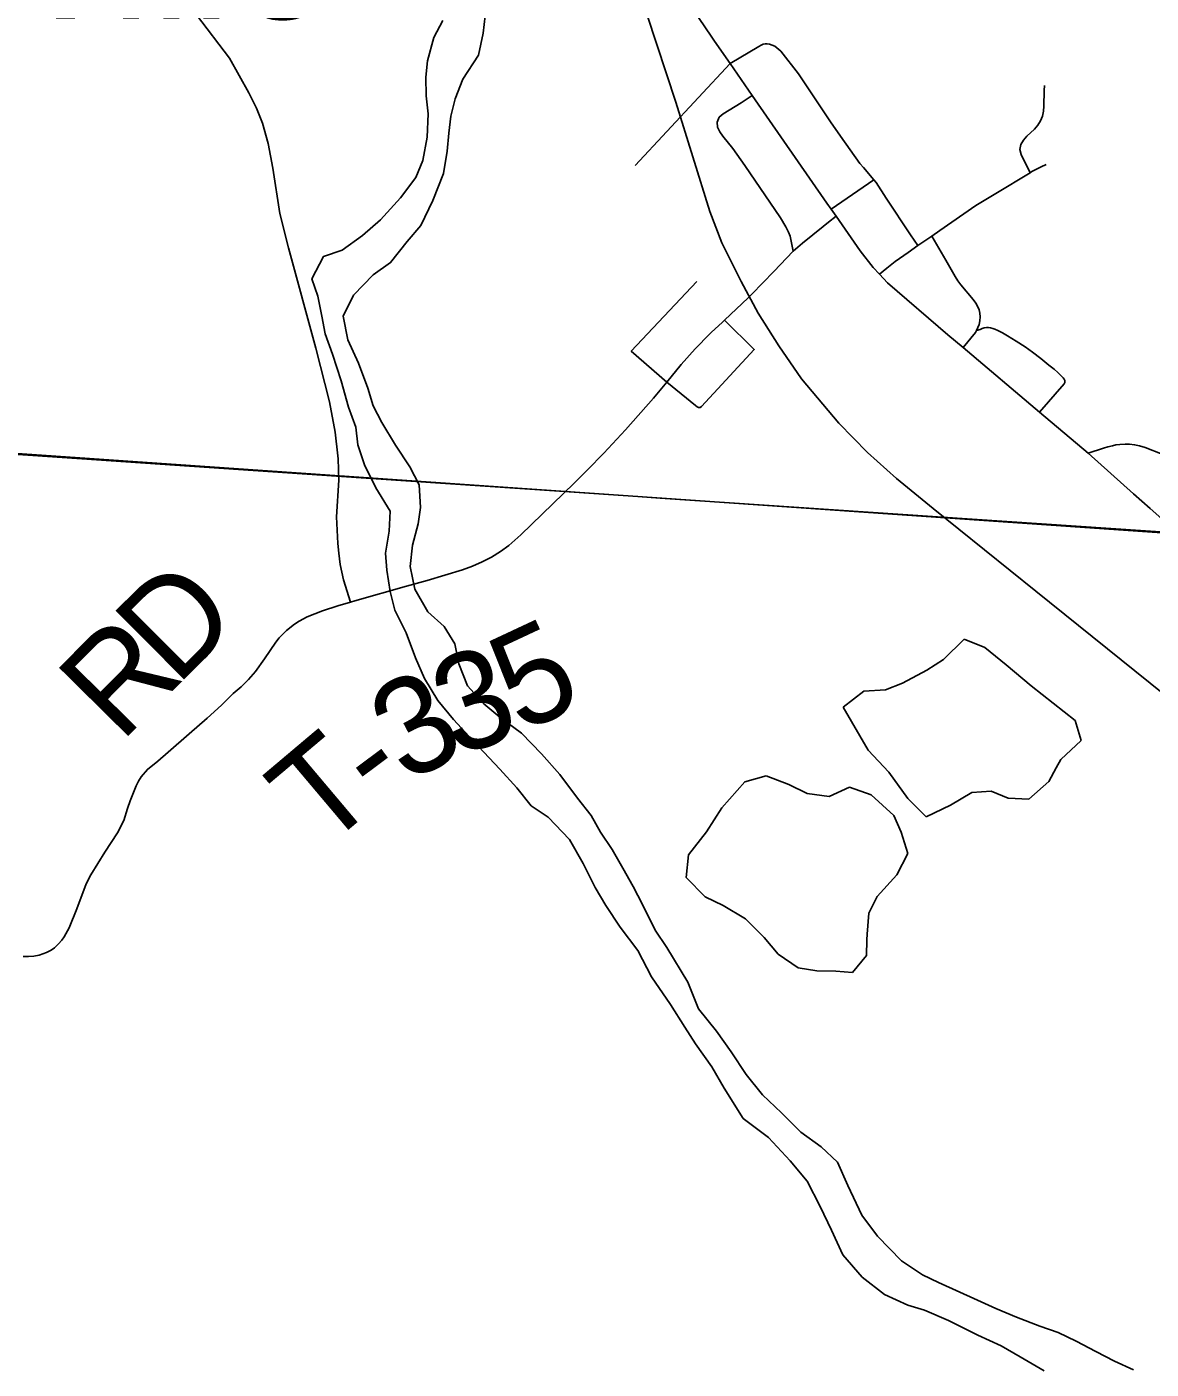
# Model space of a CAD drawing. Extents: x 39.8 to 73.8, y 13 to 35.
# Drawn here: x 46.42 to 47.078, y 27.389 to 28.175 of the extents above; entities that cross this region are included whole.
import ezdxf

# ---------------------------------------------------------------- set-up
doc = ezdxf.new("R2010")
doc.units = 0
for name, color, linetype in [('GM_X_Corporation', 7, 'Continuous'), ('GM_X_County_Road', 7, 'Continuous'), ('GM_X_Major_River', 7, 'Continuous'), ('GM_X_Minor_Lake', 7, 'Continuous'), ('GM_X_Rail_Line', 7, 'Continuous'), ('GM_X_Township_Road', 7, 'Continuous'), ('GM_X_Township_Road_Text', 7, 'Continuous'), ('GM_X_Unincorporated_Text', 7, 'Continuous')]:
    doc.layers.add(name, color=color, linetype=linetype)

msp = doc.modelspace()

# ---------------------------------------------------------------- linework, layer by layer
at = {"layer": 'GM_X_Corporation'}
msp.add_lwpolyline([(43.33042, 29.73647), (43.27257, 28.95026), (43.2721, 28.94382), (43.21308, 28.14161), (43.99916, 28.08829), (44.12704, 28.07962), (44.14223, 28.07859), (45.30639, 27.99962), (46.17667, 27.94059), (46.60108, 27.9118), (46.7316, 27.90295), (46.77749, 27.89983), (46.79052, 27.89895), (47.09502, 27.87829), (47.51487, 27.84982)], dxfattribs=at)
for points in [[(46.28582, 28.96471), (47.30013, 28.91155), (47.3019, 28.79184), (47.22222, 27.86899), (46.24519, 27.93679)], [(43.1433, 27.06498), (48.66298, 27.06498), (48.66298, 27.78088), (47.54138, 27.84843), (47.51487, 27.84982), (47.09502, 27.87829), (46.79052, 27.89895), (46.77749, 27.89983), (46.7316, 27.90295), (46.60108, 27.9118), (46.17667, 27.94059), (45.30639, 27.99962), (44.14223, 28.07859), (44.12704, 28.07962), (43.99916, 28.08829), (43.21308, 28.14161)], [(46.16091, 27.06498), (47.18234, 27.06498), (47.22222, 27.86899), (46.24519, 27.93679)]]:
    msp.add_lwpolyline(points, close=True, dxfattribs=at)
at = {"layer": 'GM_X_County_Road'}
msp.add_lwpolyline([(46.80526, 28.19183), (46.8208, 28.16863), (46.82235, 28.16639), (46.83147, 28.15325), (46.8445, 28.13446), (46.88812, 28.07159), (46.89064, 28.06796), (46.89352, 28.06383), (46.90761, 28.04354), (46.91523, 28.03381), (46.91896, 28.02991), (46.92374, 28.0249), (46.95905, 27.99454), (46.96796, 27.98699), (47.01255, 27.94928), (47.0411, 27.92512), (47.06759, 27.90145), (47.0773, 27.89289), (47.10298, 27.87025)], dxfattribs=at)
at = {"layer": 'GM_X_Major_River'}
for p, q in [((46.68689, 28.17105), (46.68865, 28.18623)), ((46.66337, 28.17842), (46.65815, 28.16852)), ((46.65815, 28.16852), (46.65449, 28.15484)), ((46.68435, 28.15814), (46.68689, 28.17105)), ((46.65449, 28.15484), (46.65344, 28.14536)), ((46.67501, 28.14404), (46.68435, 28.15814)), ((46.65344, 28.14536), (46.65353, 28.13437)), ((46.67057, 28.13263), (46.67501, 28.14404)), ((46.65353, 28.13437), (46.65476, 28.12377)), ((46.66801, 28.12238), (46.67057, 28.13263)), ((46.65476, 28.12377), (46.65412, 28.11012)), ((46.66697, 28.11251), (46.66801, 28.12238)), ((46.66592, 28.10189), (46.66697, 28.11251)), ((46.65412, 28.11012), (46.65159, 28.09646)), ((46.66376, 28.08899), (46.66592, 28.10189)), ((46.65159, 28.09646), (46.64751, 28.08657)), ((46.65747, 28.07302), (46.66376, 28.08899)), ((46.64751, 28.08657), (46.63854, 28.07474)), ((46.63854, 28.07474), (46.62692, 28.06175)), ((46.65041, 28.05855), (46.65747, 28.07302)), ((46.62692, 28.06175), (46.61641, 28.05256)), ((46.64255, 28.04901), (46.65041, 28.05855)), ((46.61641, 28.05256), (46.60437, 28.04411)), ((46.60437, 28.04411), (46.59344, 28.04022)), ((46.63282, 28.03679), (46.64255, 28.04901)), ((46.59344, 28.04022), (46.58674, 28.02728)), ((46.62266, 28.0295), (46.63282, 28.03679)), ((46.58674, 28.02728), (46.59023, 28.01708)), ((46.61104, 28.01764), (46.62266, 28.0295)), ((46.59023, 28.01708), (46.5926, 28.00535)), ((46.60509, 28.00546), (46.61104, 28.01764)), ((46.5926, 28.00535), (46.59458, 27.99514)), ((46.60786, 27.99147), (46.60509, 28.00546)), ((46.59458, 27.99514), (46.59885, 27.98305)), ((46.61403, 27.97788), (46.60786, 27.99147)), ((46.59885, 27.98305), (46.6039, 27.96756)), ((46.61946, 27.96315), (46.61403, 27.97788)), ((46.6039, 27.96756), (46.6082, 27.95206)), ((46.62257, 27.95295), (46.61946, 27.96315)), ((46.6082, 27.95206), (46.61247, 27.94035)), ((46.62758, 27.94314), (46.62257, 27.95295)), ((46.61247, 27.94035), (46.61369, 27.93013)), ((46.63564, 27.92995), (46.62758, 27.94314)), ((46.61369, 27.93013), (46.61758, 27.91842)), ((46.64407, 27.91715), (46.63564, 27.92995)), ((46.61758, 27.91842), (46.62413, 27.90484)), ((46.64946, 27.90659), (46.64407, 27.91715)), ((46.62413, 27.90484), (46.63257, 27.89127)), ((46.65034, 27.89333), (46.64946, 27.90659)), ((46.6489, 27.88384), (46.65034, 27.89333)), ((46.63257, 27.89127), (46.63192, 27.87952)), ((46.63192, 27.87952), (46.62976, 27.86662)), ((46.64561, 27.87131), (46.6489, 27.88384)), ((46.6442, 27.85879), (46.64561, 27.87131)), ((46.62976, 27.86662), (46.6306, 27.85677)), ((46.6306, 27.85677), (46.6326, 27.84428)), ((46.64697, 27.84555), (46.6442, 27.85879)), ((46.65465, 27.83236), (46.64697, 27.84555)), ((46.6326, 27.84428), (46.63534, 27.83332)), ((46.63534, 27.83332), (46.64189, 27.82012)), ((46.66419, 27.82373), (46.65465, 27.83236)), ((46.67033, 27.81356), (46.66419, 27.82373)), ((46.64189, 27.82012), (46.64732, 27.80539)), ((46.6727, 27.80183), (46.67033, 27.81356)), ((46.64732, 27.80539), (46.65272, 27.79331)), ((46.67773, 27.78899), (46.6727, 27.80183)), ((46.65272, 27.79331), (46.6604, 27.78049)), ((46.68728, 27.77847), (46.67773, 27.78899)), ((46.6604, 27.78049), (46.66958, 27.76921)), ((46.69681, 27.7706), (46.68728, 27.77847)), ((46.66958, 27.76921), (46.68104, 27.75681)), ((46.70938, 27.76124), (46.69681, 27.7706)), ((46.72121, 27.74922), (46.70938, 27.76124)), ((46.68104, 27.75681), (46.69669, 27.74028)), ((46.73191, 27.73719), (46.72121, 27.74922)), ((46.69669, 27.74028), (46.70663, 27.72938)), ((46.74225, 27.72326), (46.73191, 27.73719)), ((46.70663, 27.72938), (46.71504, 27.71885)), ((46.75028, 27.71311), (46.74225, 27.72326)), ((46.71504, 27.71885), (46.72494, 27.71212)), ((46.72494, 27.71212), (46.73754, 27.69897)), ((46.75566, 27.7033), (46.75028, 27.71311)), ((46.73754, 27.69897), (46.74561, 27.68502)), ((46.76256, 27.69313), (46.75566, 27.7033)), ((46.76871, 27.6822), (46.76256, 27.69313)), ((46.74561, 27.68502), (46.75254, 27.67106)), ((46.77486, 27.67164), (46.76871, 27.6822)), ((46.75254, 27.67106), (46.75869, 27.66051)), ((46.78025, 27.66108), (46.77486, 27.67164)), ((46.75869, 27.66051), (46.76712, 27.6477)), ((46.78757, 27.64599), (46.78025, 27.66108)), ((46.76712, 27.6477), (46.77746, 27.63415)), ((46.79447, 27.63582), (46.78757, 27.64599)), ((46.77746, 27.63415), (46.78554, 27.61869)), ((46.80675, 27.61547), (46.79447, 27.63582)), ((46.78554, 27.61869), (46.79665, 27.6025)), ((46.81294, 27.59999), (46.80675, 27.61547)), ((46.79665, 27.6025), (46.80509, 27.58931)), ((46.82365, 27.58683), (46.81294, 27.59999)), ((46.80509, 27.58931), (46.81123, 27.57952)), ((46.83208, 27.57478), (46.82365, 27.58683)), ((46.81123, 27.57952), (46.8208, 27.56596)), ((46.8409, 27.56159), (46.83208, 27.57478)), ((46.8208, 27.56596), (46.8281, 27.55352)), ((46.85046, 27.54956), (46.8409, 27.56159)), ((46.8281, 27.55352), (46.83923, 27.53581)), ((46.86152, 27.53905), (46.85046, 27.54956)), ((46.87297, 27.52778), (46.86152, 27.53905)), ((46.83923, 27.53581), (46.85408, 27.52458)), ((46.85408, 27.52458), (46.86669, 27.51105)), ((46.88478, 27.51917), (46.87297, 27.52778)), ((46.89432, 27.51017), (46.88478, 27.51917)), ((46.86669, 27.51105), (46.87663, 27.49902)), ((46.90049, 27.49658), (46.89432, 27.51017)), ((46.87663, 27.49902), (46.88433, 27.48431)), ((46.90858, 27.47922), (46.90049, 27.49658)), ((46.88433, 27.48431), (46.89088, 27.47035)), ((46.91777, 27.4668), (46.90858, 27.47922)), ((46.89088, 27.47035), (46.89744, 27.45601)), ((46.9319, 27.45253), (46.91777, 27.4668)), ((46.89744, 27.45601), (46.9089, 27.44285)), ((46.94408, 27.44431), (46.9319, 27.45253)), ((46.9089, 27.44285), (46.92186, 27.43274)), ((46.95358, 27.43984), (46.94408, 27.44431)), ((46.97637, 27.42944), (46.95358, 27.43984)), ((46.92186, 27.43274), (46.93553, 27.42642)), ((46.98701, 27.42461), (46.97637, 27.42944)), ((46.93553, 27.42642), (46.9454, 27.42348)), ((46.9454, 27.42348), (46.95945, 27.41754)), ((46.99916, 27.41942), (46.98701, 27.42461)), ((46.95945, 27.41754), (46.97655, 27.40898)), ((47.01283, 27.41424), (46.99916, 27.41942)), ((47.02345, 27.41055), (47.01283, 27.41424)), ((46.97655, 27.40898), (46.99022, 27.40266)), ((47.03409, 27.40534), (47.02345, 27.41055)), ((47.0455, 27.39938), (47.03409, 27.40534)), ((46.99022, 27.40266), (47.00125, 27.39632)), ((47.05652, 27.3938), (47.0455, 27.39938)), ((47.00125, 27.39632), (47.01532, 27.38812)), ((47.06754, 27.38859), (47.05652, 27.3938))]:
    msp.add_line(p, q, dxfattribs=at)
for points in [[(46.68865, 28.18623), (46.68689, 28.17105), (46.68435, 28.15814), (46.67501, 28.14404)], [(46.66337, 28.17842), (46.65815, 28.16852), (46.65449, 28.15484)], [(46.65449, 28.15484), (46.65344, 28.14536), (46.65353, 28.13437), (46.65476, 28.12377), (46.65412, 28.11012), (46.65159, 28.09646), (46.64751, 28.08657), (46.63854, 28.07474), (46.62692, 28.06175), (46.61641, 28.05256), (46.60437, 28.04411), (46.59344, 28.04022), (46.58674, 28.02728), (46.59023, 28.01708), (46.5926, 28.00535), (46.59458, 27.99514), (46.59885, 27.98305), (46.6039, 27.96756), (46.6082, 27.95206), (46.61247, 27.94035), (46.61369, 27.93013), (46.61758, 27.91842), (46.62413, 27.90484), (46.63257, 27.89127), (46.63192, 27.87952), (46.62976, 27.86662), (46.6306, 27.85677), (46.6326, 27.84428), (46.63534, 27.83332), (46.64189, 27.82012), (46.64732, 27.80539), (46.65272, 27.79331), (46.6604, 27.78049), (46.66958, 27.76921), (46.68104, 27.75681), (46.69669, 27.74028), (46.70663, 27.72938), (46.71504, 27.71885), (46.72494, 27.71212), (46.73754, 27.69897), (46.74561, 27.68502), (46.75254, 27.67106), (46.75869, 27.66051), (46.76712, 27.6477), (46.77746, 27.63415), (46.78554, 27.61869), (46.79665, 27.6025), (46.80509, 27.58931), (46.81123, 27.57952), (46.8208, 27.56596), (46.8281, 27.55352), (46.83923, 27.53581), (46.85408, 27.52458), (46.86669, 27.51105), (46.87663, 27.49902), (46.88433, 27.48431), (46.89088, 27.47035), (46.89744, 27.45601), (46.9089, 27.44285), (46.92186, 27.43274), (46.93553, 27.42642), (46.9454, 27.42348), (46.95945, 27.41754), (46.97655, 27.40898), (46.99022, 27.40266), (47.00125, 27.39632), (47.01532, 27.38812)], [(46.67501, 28.14404), (46.67057, 28.13263), (46.66801, 28.12238), (46.66697, 28.11251), (46.66592, 28.10189), (46.66376, 28.08899), (46.65747, 28.07302), (46.65041, 28.05855), (46.64255, 28.04901), (46.63282, 28.03679), (46.62266, 28.0295), (46.61104, 28.01764), (46.60509, 28.00546), (46.60786, 27.99147), (46.61403, 27.97788), (46.61946, 27.96315), (46.62257, 27.95295), (46.62758, 27.94314), (46.63564, 27.92995), (46.64407, 27.91715), (46.64946, 27.90659), (46.65034, 27.89333), (46.6489, 27.88384), (46.64561, 27.87131), (46.6442, 27.85879), (46.64697, 27.84555), (46.65465, 27.83236), (46.66419, 27.82373), (46.67033, 27.81356), (46.6727, 27.80183), (46.67773, 27.78899), (46.68728, 27.77847), (46.69681, 27.7706), (46.70938, 27.76124), (46.72121, 27.74922), (46.73191, 27.73719), (46.74225, 27.72326), (46.75028, 27.71311), (46.75566, 27.7033), (46.76256, 27.69313), (46.76871, 27.6822), (46.77486, 27.67164), (46.78025, 27.66108), (46.78757, 27.64599), (46.79447, 27.63582), (46.80675, 27.61547), (46.81294, 27.59999), (46.82365, 27.58683), (46.83208, 27.57478), (46.8409, 27.56159), (46.85046, 27.54956), (46.86152, 27.53905), (46.87297, 27.52778), (46.88478, 27.51917), (46.89432, 27.51017), (46.90049, 27.49658), (46.90858, 27.47922), (46.91777, 27.4668), (46.9319, 27.45253), (46.94408, 27.44431), (46.95358, 27.43984), (46.97637, 27.42944), (46.98701, 27.42461), (46.99916, 27.41942), (47.01283, 27.41424), (47.02345, 27.41055), (47.03409, 27.40534), (47.0455, 27.39938), (47.05652, 27.3938), (47.06754, 27.38859)]]:
    msp.add_lwpolyline(points, dxfattribs=at)
at = {"layer": 'GM_X_Minor_Lake'}
for p, q in [((46.96846, 27.81627), (46.95645, 27.80442)), ((46.98061, 27.81146), (46.96846, 27.81627)), ((46.99318, 27.80134), (46.98061, 27.81146)), ((46.94667, 27.79827), (46.93236, 27.79056)), ((46.95645, 27.80442), (46.94667, 27.79827)), ((47.00767, 27.78897), (46.99318, 27.80134)), ((46.93236, 27.79056), (46.92255, 27.78668)), ((46.9097, 27.7858), (46.89767, 27.7766)), ((46.92255, 27.78668), (46.9097, 27.7858)), ((47.02062, 27.77886), (47.00767, 27.78897)), ((46.89767, 27.7766), (46.91227, 27.75134)), ((47.03358, 27.76874), (47.02062, 27.77886)), ((47.03708, 27.75703), (47.03358, 27.76874)), ((46.91227, 27.75134), (46.92449, 27.73857)), ((47.02507, 27.74593), (47.03708, 27.75703)), ((47.02241, 27.74106), (47.02507, 27.74593)), ((46.85262, 27.7364), (46.84016, 27.73287)), ((46.8659, 27.73121), (46.85262, 27.7364)), ((46.92449, 27.73857), (46.9356, 27.72313)), ((47.018, 27.73298), (47.02241, 27.74106)), ((46.84016, 27.73287), (46.82667, 27.71759)), ((46.87654, 27.726), (46.8659, 27.73121)), ((46.90149, 27.72964), (46.88942, 27.72423)), ((46.91401, 27.72521), (46.90149, 27.72964)), ((46.97302, 27.72651), (46.98437, 27.72737)), ((46.98437, 27.72737), (46.99424, 27.72329)), ((47.00636, 27.72264), (47.018, 27.73298)), ((46.88942, 27.72423), (46.87654, 27.726)), ((46.92736, 27.7132), (46.91401, 27.72521)), ((46.9356, 27.72313), (46.94629, 27.71224)), ((46.9606, 27.71919), (46.97302, 27.72651)), ((46.99424, 27.72329), (47.00636, 27.72264)), ((46.82667, 27.71759), (46.81772, 27.70349)), ((46.93161, 27.70339), (46.92736, 27.7132)), ((46.94629, 27.71224), (46.9606, 27.71919)), ((46.81772, 27.70349), (46.80724, 27.69013)), ((46.9355, 27.69092), (46.93161, 27.70339)), ((46.80724, 27.69013), (46.80584, 27.67685)), ((46.92917, 27.67836), (46.9355, 27.69092)), ((46.80584, 27.67685), (46.81691, 27.66559)), ((46.91755, 27.66575), (46.92917, 27.67836)), ((46.81691, 27.66559), (46.82755, 27.66038)), ((46.91272, 27.65585), (46.91755, 27.66575)), ((46.82755, 27.66038), (46.84048, 27.65254)), ((46.84048, 27.65254), (46.85155, 27.64165)), ((46.91169, 27.64371), (46.91272, 27.65585)), ((46.85155, 27.64165), (46.85958, 27.63187)), ((46.91162, 27.64029), (46.91169, 27.64371)), ((46.91142, 27.63121), (46.91162, 27.64029)), ((46.85958, 27.63187), (46.87138, 27.62402)), ((46.90319, 27.62128), (46.91142, 27.63121)), ((46.87138, 27.62402), (46.88237, 27.62223)), ((46.88237, 27.62223), (46.89334, 27.62195)), ((46.89334, 27.62195), (46.90319, 27.62128))]:
    msp.add_line(p, q, dxfattribs=at)
at = {"layer": 'GM_X_Rail_Line'}
msp.add_lwpolyline([(46.69268, 28.45583), (46.79975, 28.13066), (46.81961, 28.06668), (46.82663, 28.04831), (46.83799, 28.02577), (46.84789, 28.00716), (46.86005, 27.98803), (46.87337, 27.96868), (46.89525, 27.94268), (46.91195, 27.92567), (46.92897, 27.91044), (46.95032, 27.8929), (47.01046, 27.84438), (47.16024, 27.72389), (47.24434, 27.65129), (47.28129, 27.6165), (47.31454, 27.58433), (47.35954, 27.53887), (47.39016, 27.50624), (47.44583, 27.44376), (47.49315, 27.38949)], dxfattribs=at)
at = {"layer": 'GM_X_Township_Road'}
msp.add_line((46.77596, 28.0935), (46.83147, 28.15325), dxfattribs=at)
for points in [[(46.51919, 28.18178), (46.53856, 28.15645), (46.54987, 28.13615), (46.55436, 28.12716), (46.55783, 28.11839), (46.5612, 28.10651), (46.5639, 28.09198), (46.56806, 28.06546), (46.57299, 28.04529), (46.58901, 27.98672), (46.59698, 27.9552), (46.60038, 27.93746), (46.60195, 27.92355), (46.60214, 27.92184), (46.60249, 27.90943), (46.60112, 27.88785), (46.6019, 27.87236), (46.60255, 27.86668)], [(46.89064, 28.06796), (46.91557, 28.08518), (46.9096, 28.09246), (46.90745, 28.09474), (46.89617, 28.11077), (46.89026, 28.11908), (46.87146, 28.14718), (46.8612, 28.16041), (46.86014, 28.16152), (46.85896, 28.16254), (46.85763, 28.16342), (46.85611, 28.16406), (46.85459, 28.16452), (46.85331, 28.1647), (46.85204, 28.16475), (46.85088, 28.16452), (46.84973, 28.16402), (46.8484, 28.16332), (46.83147, 28.15325)], [(47.00708, 28.08929), (47.00185, 28.09992), (47.00119, 28.10289), (47.00165, 28.10584), (47.00323, 28.10842), (47.00527, 28.11067), (47.00964, 28.11486), (47.01159, 28.11714), (47.01316, 28.1197), (47.01433, 28.12247), (47.01501, 28.12538), (47.01525, 28.12838), (47.01537, 28.13741), (47.01559, 28.14042)], [(46.86852, 28.04343), (46.86661, 28.05212), (46.86572, 28.05457), (46.86414, 28.05773), (46.86094, 28.06297), (46.84011, 28.09352), (46.83306, 28.10359), (46.82725, 28.11077), (46.82549, 28.1133), (46.82421, 28.11603), (46.82398, 28.11897), (46.82508, 28.12181), (46.82741, 28.1238), (46.83792, 28.13021), (46.84041, 28.13182), (46.8445, 28.13446)], [(46.91896, 28.02991), (46.92335, 28.03352), (46.92812, 28.03745), (46.93574, 28.04273), (46.94146, 28.04668), (46.94954, 28.05229), (46.95425, 28.05553), (46.97529, 28.07021), (46.98701, 28.07725), (47.00708, 28.08929), (47.00821, 28.08998), (47.01368, 28.09286), (47.01647, 28.09417)], [(46.94146, 28.04668), (46.93704, 28.05309), (46.92278, 28.07443), (46.91692, 28.08367), (46.91557, 28.08518)], [(46.89352, 28.06383), (46.88917, 28.0604), (46.88596, 28.05786), (46.8738, 28.04819), (46.86852, 28.04343), (46.8571, 28.03152), (46.8442, 28.01834)], [(46.96796, 27.98699), (46.97508, 27.99579), (46.97583, 27.99695), (46.97735, 28.00057), (46.97775, 28.00269), (46.97796, 28.00507), (46.97775, 28.0072), (46.9773, 28.00918), (46.97634, 28.0113), (46.97528, 28.01302), (46.97376, 28.01515), (46.96653, 28.02375), (46.96477, 28.0261), (46.96325, 28.02862), (46.9578, 28.03824), (46.94954, 28.05229)], [(46.7945, 27.96666), (46.77364, 27.98492), (46.81212, 28.0257)], [(46.8442, 28.01834), (46.84205, 28.01614), (46.82827, 28.00312), (46.827, 28.00192), (46.82044, 27.99573)], [(46.7945, 27.96666), (46.81131, 27.95305), (46.81231, 27.95223), (46.81302, 27.95188), (46.81404, 27.95197), (46.81471, 27.95248), (46.84563, 27.98589), (46.8283, 28.0031)], [(46.82044, 27.99573), (46.81972, 27.99505), (46.81107, 27.98628), (46.80287, 27.97707), (46.7945, 27.96666), (46.78676, 27.95742), (46.77039, 27.93879), (46.75768, 27.92514), (46.74803, 27.91543)], [(47.01255, 27.94928), (47.02699, 27.96585), (47.02738, 27.96649), (47.0275, 27.96715), (47.02741, 27.9678), (47.02713, 27.96843), (47.02655, 27.96925), (47.02343, 27.97233), (47.02113, 27.97433), (47.01817, 27.97678), (47.01344, 27.98051), (47.00843, 27.98435), (47.00422, 27.98738), (46.99894, 27.99084), (46.9939, 27.99383), (46.99093, 27.99554), (46.98935, 27.99639), (46.98814, 27.99702), (46.98657, 27.99774), (46.98535, 27.9982), (46.98403, 27.99853), (46.98283, 27.99869), (46.98156, 27.99869), (46.9803, 27.9985), (46.97909, 27.99814), (46.97784, 27.99761), (46.97583, 27.99695)], [(47.0411, 27.92512), (47.05013, 27.92815), (47.0526, 27.92888), (47.05525, 27.92956), (47.05738, 27.92998), (47.05973, 27.93024), (47.06276, 27.93041), (47.06537, 27.93037), (47.06823, 27.93011), (47.07117, 27.92947), (47.07441, 27.92845), (47.08438, 27.92461)], [(46.74803, 27.91543), (46.74734, 27.91474), (46.74019, 27.90755), (46.70904, 27.87731), (46.70202, 27.87123), (46.69704, 27.86758), (46.69191, 27.86438), (46.68647, 27.86153)], [(46.68647, 27.86153), (46.68081, 27.85904), (46.67497, 27.85692), (46.65419, 27.85068), (46.64213, 27.8473), (46.61194, 27.83868), (46.60927, 27.83792), (46.60189, 27.83581), (46.59287, 27.83286), (46.58402, 27.82941), (46.57921, 27.82687), (46.57664, 27.8252), (46.57184, 27.82142), (46.56963, 27.8193), (46.56756, 27.81704), (46.56566, 27.81459), (46.55909, 27.80487), (46.5537, 27.7974), (46.54966, 27.79276), (46.54534, 27.78838), (46.54067, 27.78444), (46.53395, 27.77798), (46.52962, 27.77379), (46.52548, 27.77012), (46.51489, 27.76094), (46.50269, 27.7501), (46.49648, 27.74492), (46.49044, 27.74009), (46.48675, 27.73569), (46.48525, 27.73328), (46.48396, 27.73054), (46.48043, 27.72169), (46.47887, 27.71725), (46.47658, 27.71026), (46.47293, 27.70306), (46.46563, 27.69166), (46.45743, 27.6784), (46.45465, 27.67308), (46.44921, 27.65851), (46.44461, 27.64739), (46.44177, 27.64203), (46.44042, 27.64011), (46.43839, 27.63793), (46.43606, 27.63572), (46.4342, 27.63425), (46.4314, 27.63289), (46.4272, 27.63138), (46.42392, 27.63087), (46.42085, 27.63063), (46.41779, 27.63066)], [(46.60255, 27.86668), (46.60332, 27.86006), (46.60516, 27.85097), (46.60927, 27.83792)]]:
    msp.add_lwpolyline(points, dxfattribs=at)

# ---------------------------------------------------------------- texts
at = {"layer": 'GM_X_Township_Road_Text'}
for s, rotation, p in [('D', 44.86347, (46.5075, 27.78832)), ('R', 45.356, (46.4748, 27.75521)), ('5', 25.0576, (46.70905, 27.761)), ('3', 19.52779, (46.67054, 27.74704)), ('3', 27.86372, (46.64159, 27.73156)), ('T', 40.14576, (46.59306, 27.69201)), ('-', 36.70752, (46.62485, 27.71885))]:
    msp.add_text(s, height=0.05682, rotation=rotation, dxfattribs=at).set_placement(p)
at = {"layer": 'GM_X_Unincorporated_Text'}
msp.add_text('Haydenville', height=0.0789773, rotation=0.00001, dxfattribs=at).set_placement((46.05237, 28.17947))

doc.saveas('drawing.dxf')
